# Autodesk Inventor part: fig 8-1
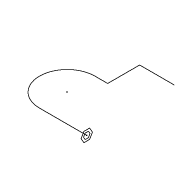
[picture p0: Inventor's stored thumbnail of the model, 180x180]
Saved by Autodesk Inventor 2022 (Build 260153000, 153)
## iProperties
Created: 2004-05
Part Number: fig 8-1
Document SubType Name: Modeling
Designer: CADCIM Technologies
Manufacturer: Standard
Standards Organization: Custom
Density: 1 g/cm^3
Material: Generic
Appearance: Default
Author: CADCIM Technologies
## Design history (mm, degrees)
sketch "Sketch1"
  geometry: L1 (-42.583, 3.219)-(-90.066, 3.219); L2 (-90.066, 58.92)-(-77.282, 58.92); L3 (-77.282, 58.92)-(-77.282, 91.063); L4 (-77.282, 91.063)-(-42.583, 91.063); A1 r 27.851 centre (-90.066, 31.07) between (-90.066, 58.92) and (-90.066, 3.219)
  constraints: 8 end point, 2 parallel, 2 point on circle, 2 tangent, 1 centre point, 1 perpendicular
workplane "Work Plane2"
sketch "Sketch2"
  geometry: L1 (-5.697, 0)-(-2.849, 4.934); L2 (-2.849, 4.934)-(2.849, 4.934); L3 (2.849, 4.934)-(5.697, 0); L4 (5.697, 0)-(2.849, -4.934); L5 (2.849, -4.934)-(-2.849, -4.934); L6 (-2.849, -4.934)-(-5.697, 0); L7 (-3.256, 0)-(-1.628, 2.819); L8 (-1.628, 2.819)-(1.628, 2.819); L9 (1.628, 2.819)-(3.256, 0); L10 (3.256, 0)-(1.628, -2.819); L11 (1.628, -2.819)-(-1.628, -2.819); L12 (-1.628, -2.819)-(-3.256, 0); 2 further points
  constraints: 24 end point, 1 coincident, 22 other
